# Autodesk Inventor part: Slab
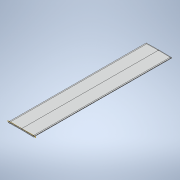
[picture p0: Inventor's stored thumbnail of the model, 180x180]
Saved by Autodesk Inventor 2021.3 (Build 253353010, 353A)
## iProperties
Created: 2021-11
Part Number: Slab
Material: Concrete, Broom Finish
Document SubType Name: Modeling
Designer: u1426
Density: 2.40731 g/cm^3
Appearance: Flat - Broom Gray
Author: u1426
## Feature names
1. Sweep1
2. Extrusion1
3. Chamfer1
4. Extrusion2
5. Chamfer2
6. Sweep2
7. Sweep3
8. Sweep4
9. Sweep5
10. Sweep6
11. Sweep7
## Parameters: d0 = 203.2 mm, d1 = 203.2 mm, d2 = 508 mm, d3 = 5486.4 mm, d4 = 5486.4 mm, d5 = 508 mm, d6 = 109.728 mm, d7 = 109.728 mm, d8 = 12.7 mm, d9 = 1219.2 mm, d10 = 1219.2 mm, d11 = 1219.2 mm, d12 = 1219.2 mm, d13 = 12.7 mm, d14 = 1930.4 mm, d15 = 1930.4 mm, d16 = 965.2 mm, d17 = 965.2 mm, d18 = 209.55 mm, d19 = 209.55 mm, d20 = 209.55 mm, d21 = 209.55 mm, d22 = 247.65 mm, d23 = 247.65 mm, d24 = 247.65 mm, d25 = 247.65 mm, d26 = 64414.4 mm, d27 = 257.6576 mm, d28 = 0, d29 = 0, d30 = 76.2 mm, d31 = 76.2 mm, d32 = 76.2 mm, d33 = 76.2 mm, d34 = 76.2 mm, d35 = 279.4 mm, d36 = 0, d37 = 76.2 mm, d38 = 3.175 mm, d39 = 45 deg, d40 = 76.2 mm, d41 = 76.2 mm, d42 = 76.2 mm, d43 = 76.2 mm, d44 = 76.2 mm, d45 = 279.4 mm, d46 = 0, d47 = 76.2 mm, d48 = 3.175 mm, d49 = 45 deg, d50 = 209.55 mm, d57 = 25.4 mm, d58 = 45 deg, d59 = 0, d60 = 0, d61 = 25.4 mm, d62 = 45 deg, d63 = 0, d64 = 0, d65 = -355.6 mm, d68 = 45 deg, d69 = 22.5 deg, d75 = 0, d76 = 0, d77 = 22.5 deg, d78 = 45 deg, d79 = 12.7 mm, d80 = 50.8 mm, d81 = 0, d82 = 0, d83 = 12.7 mm, d84 = 19.05 mm, d85 = 19.05 mm, d86 = 19.05 mm, d87 = 19.05 mm, d88 = 50.8 mm, d91 = 0, d92 = 0, d96 = 0, d97 = 0
